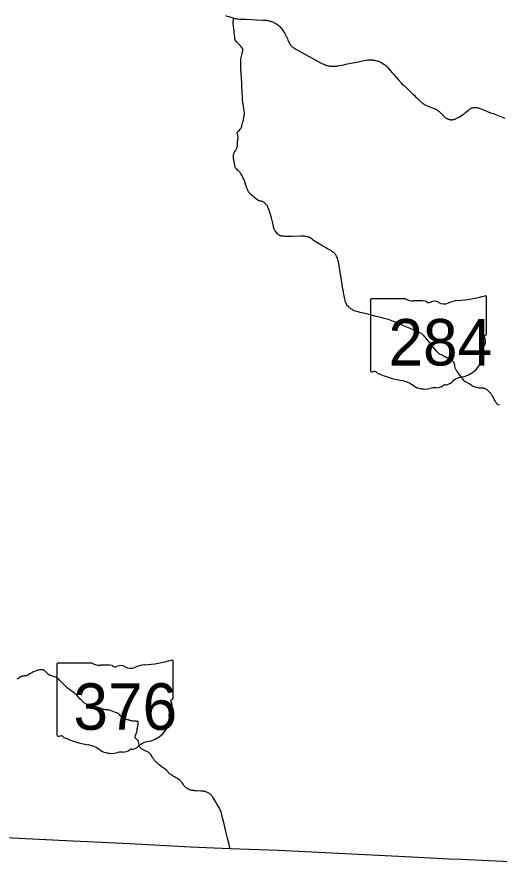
# Model space of a CAD drawing. Extents: x 1761803 to 2441803, y 509895 to 949895.
# Drawn here: x 2145336 to 2174217, y 736190 to 786865 of the extents above; entities that cross this region are included whole.
import ezdxf

# ---------------------------------------------------------------- set-up
doc = ezdxf.new("R2010")
doc.units = 0
for name, color, linetype in [('GM_X_County', 7, 'Continuous'), ('GM_X_Minor_Lake', 7, 'Continuous'), ('GM_X_Township_Road', 7, 'Continuous')]:
    doc.layers.add(name, color=color, linetype=linetype)

msp = doc.modelspace()

# ---------------------------------------------------------------- linework, layer by layer
at = {"layer": 'GM_X_County'}
msp.add_lwpolyline([(2176490, 736190), (2173590, 736330), (2171974, 736412), (2171228, 736429), (2168996, 736548), (2160995, 736937), (2158105, 737039), (2155729, 737139), (2152072, 737341), (2147863, 737541), (2144231, 737722)], dxfattribs=at)
at = {"layer": 'GM_X_Minor_Lake'}
for points in [[(2157833, 786941), (2157929, 786911), (2157991, 786892), (2158085, 786864), (2158271, 786808), (2158333, 786789)], [(2164420, 772630), (2164403, 772654), (2164373, 772693), (2164339, 772730), (2164303, 772764), (2164265, 772795), (2164225, 772825), (2164184, 772852), (2164142, 772878), (2164099, 772901), (2164026, 772938), (2163967, 772966), (2163909, 772996), (2163781, 773068), (2163738, 773093), (2163667, 773134), (2163597, 773176), (2163512, 773226), (2163456, 773259), (2163372, 773310), (2163303, 773354), (2163192, 773424), (2163137, 773460), (2163083, 773497), (2163018, 773546), (2162952, 773595), (2162911, 773622), (2162868, 773647), (2162823, 773669), (2162777, 773687), (2162730, 773702), (2162682, 773713), (2162633, 773721), (2162568, 773727), (2162354, 773728), (2161831, 773716), (2161453, 773719), (2161404, 773720), (2161323, 773725), (2161258, 773731), (2161206, 773739), (2161157, 773747), (2161110, 773760), (2161096, 773766), (2161069, 773776), (2161038, 773794), (2161005, 773821), (2160973, 773851), (2160800, 774045), (2160777, 774078), (2160755, 774114), (2160741, 774147), (2160728, 774185), (2160718, 774221), (2160707, 774280), (2160685, 774426), (2160670, 774506), (2160649, 774602), (2160613, 774745), (2160588, 774839), (2160570, 774902), (2160529, 775026), (2160463, 775212), (2160390, 775435), (2160374, 775475), (2160359, 775506), (2160343, 775535), (2160325, 775562), (2160305, 775588), (2160283, 775613), (2160248, 775648), (2160200, 775693), (2160137, 775747), (2160073, 775795), (2160048, 775805), (2160017, 775812), (2159957, 775828), (2159911, 775836), (2159863, 775849), (2159831, 775859), (2159806, 775871), (2159773, 775886), (2159712, 775926), (2159611, 776008), (2159548, 776061), (2159450, 776147), (2159378, 776213), (2159331, 776258), (2159296, 776293), (2159263, 776329), (2159243, 776354), (2159214, 776394), (2159189, 776433), (2159161, 776484), (2159140, 776521), (2159122, 776560), (2159102, 776611), (2159080, 776679), (2159062, 776736), (2159047, 776806), (2159033, 776860), (2159018, 776910), (2158996, 776970), (2158965, 777045), (2158921, 777151), (2158894, 777211), (2158866, 777270), (2158828, 777343), (2158796, 777400), (2158763, 777457), (2158727, 777512), (2158708, 777539), (2158687, 777564), (2158666, 777589), (2158633, 777625), (2158598, 777660), (2158536, 777714), (2158488, 777759), (2158466, 777782), (2158443, 777805), (2158423, 777832), (2158409, 777858), (2158402, 777884), (2158390, 777933), (2158384, 777981), (2158373, 778049), (2158359, 778128), (2158344, 778192), (2158329, 778256), (2158321, 778304), (2158316, 778353), (2158313, 778403), (2158312, 778453), (2158312, 778569), (2158318, 778622), (2158326, 778660), (2158340, 778697), (2158370, 778757), (2158423, 778854), (2158486, 778971), (2158503, 779012), (2158521, 779063), (2158531, 779102), (2158541, 779147), (2158547, 779211), (2158547, 779314), (2158548, 779365), (2158554, 779405), (2158563, 779459), (2158575, 779527), (2158584, 779580), (2158585, 779611), (2158587, 779647), (2158584, 779682), (2158577, 779724), (2158564, 779769), (2158540, 779846), (2158531, 779881), (2158530, 779905), (2158533, 779928), (2158538, 779944), (2158544, 779958), (2158552, 779972), (2158568, 779992), (2158594, 780020), (2158664, 780091), (2158709, 780136), (2158730, 780161), (2158749, 780189), (2158765, 780217), (2158779, 780248), (2158791, 780278), (2158810, 780341), (2158836, 780436), (2158855, 780515), (2158878, 780611), (2158901, 780706), (2158931, 780834), (2158947, 780915), (2158956, 780963), (2158961, 781013), (2158963, 781046), (2158962, 781079), (2158960, 781112), (2158954, 781161), (2158942, 781242), (2158885, 781644), (2158874, 781742), (2158856, 781905), (2158848, 782003), (2158840, 782166), (2158836, 782248), (2158825, 782441), (2158810, 782716), (2158807, 782781), (2158805, 782829), (2158803, 782876), (2158802, 782907), (2158756, 783764), (2158742, 784069), (2158740, 784151), (2158741, 784216), (2158746, 784282), (2158754, 784363), (2158766, 784444), (2158780, 784510), (2158800, 784598), (2158822, 784675), (2158840, 784750), (2158853, 784810), (2158861, 784859), (2158863, 784875), (2158863, 784892), (2158863, 784909), (2158861, 784925), (2158858, 784941), (2158854, 784958), (2158849, 784973), (2158842, 784989), (2158834, 785003), (2158825, 785017), (2158815, 785030), (2158794, 785055), (2158726, 785126), (2158682, 785174), (2158597, 785273), (2158554, 785321), (2158497, 785379), (2158453, 785427), (2158434, 785453), (2158417, 785480), (2158404, 785509), (2158398, 785524), (2158390, 785555), (2158385, 785587), (2158381, 785619), (2158379, 785667), (2158375, 785788), (2158368, 785855), (2158358, 785937), (2158345, 786025), (2158329, 786138), (2158303, 786350), (2158295, 786431), (2158286, 786496), (2158284, 786529), (2158284, 786561), (2158290, 786609), (2158299, 786657), (2158316, 786721), (2158333, 786789)], [(2158333, 786789), (2158386, 786777), (2158454, 786765), (2158534, 786754), (2158594, 786748)], [(2158594, 786748), (2158596, 786748), (2158715, 786740), (2159059, 786725), (2159682, 786696), (2160059, 786680), (2160190, 786672), (2160256, 786666), (2160321, 786657), (2160386, 786645), (2160450, 786631), (2160513, 786614), (2160576, 786593), (2160637, 786569), (2160697, 786542), (2160751, 786516), (2160797, 786489), (2160842, 786464), (2160898, 786429), (2160952, 786391), (2161003, 786350), (2161054, 786308), (2161102, 786263), (2161147, 786215), (2161191, 786166), (2161232, 786115), (2161271, 786062), (2161327, 785977), (2161351, 785936), (2161380, 785878), (2161445, 785745), (2161535, 785551), (2161569, 785477), (2161624, 785358), (2161660, 785285), (2161683, 785245), (2161711, 785201), (2161730, 785175), (2161762, 785138), (2161797, 785103), (2161833, 785071), (2161873, 785042), (2161928, 785007), (2162042, 784942), (2162631, 784619), (2163019, 784405), (2163027, 784401), (2163566, 784105), (2163653, 784060), (2163712, 784031), (2163772, 784006), (2163833, 783984), (2163896, 783965), (2163975, 783944), (2164039, 783931), (2164104, 783921), (2164185, 783912), (2164250, 783908), (2164315, 783907), (2164381, 783910), (2164446, 783916), (2164511, 783925), (2164640, 783948), (2164913, 784004), (2165041, 784031), (2165346, 784094), (2165555, 784137), (2165667, 784160), (2165780, 784183), (2166165, 784262), (2166246, 784276), (2166328, 784287), (2166393, 784293), (2166459, 784295), (2166525, 784295), (2166591, 784292), (2166646, 784289), (2166703, 784282), (2166758, 784273), (2166820, 784260), (2166888, 784242), (2166949, 784222), (2166993, 784206), (2167039, 784188), (2167086, 784167), (2167134, 784144), (2167165, 784127), (2167211, 784102), (2167256, 784075), (2167313, 784037), (2167367, 783997), (2167427, 783948), (2167464, 783915), (2167510, 783869), (2167611, 783761), (2167697, 783662), (2167813, 783525), (2167856, 783476), (2167911, 783415), (2167974, 783340), (2168049, 783254), (2168168, 783118), (2168332, 782935), (2168399, 782864), (2168492, 782772), (2168682, 782591), (2168825, 782456), (2168867, 782418), (2168921, 782367), (2169076, 782220), (2169125, 782177), (2169220, 782086), (2169268, 782041), (2169411, 781906), (2169580, 781750), (2169629, 781708), (2169668, 781678), (2169722, 781641), (2169777, 781607), (2169821, 781584), (2169880, 781557), (2169971, 781519), (2170109, 781467), (2170325, 781388), (2170386, 781363), (2170430, 781342), (2170473, 781317), (2170514, 781290), (2170553, 781260), (2170603, 781216), (2170792, 781035), (2170875, 780956), (2170950, 780884), (2170987, 780850), (2171019, 780826), (2171061, 780796), (2171101, 780773), (2171150, 780749), (2171197, 780732), (2171241, 780721), (2171278, 780714), (2171316, 780709), (2171360, 780707), (2171407, 780709), (2171444, 780713), (2171485, 780718), (2171506, 780723), (2171518, 780726), (2171546, 780735), (2171583, 780748), (2171623, 780767), (2171668, 780792), (2171768, 780849), (2171839, 780890), (2171936, 780949), (2172033, 781011), (2172113, 781065), (2172166, 781103), (2172230, 781154), (2172359, 781267), (2172421, 781317), (2172462, 781347), (2172503, 781372), (2172540, 781393), (2172571, 781407), (2172601, 781417), (2172633, 781428), (2172667, 781436), (2172717, 781444), (2172762, 781446), (2172799, 781446), (2172838, 781444), (2172882, 781440), (2172912, 781435), (2172940, 781428), (2172968, 781419), (2173026, 781399), (2173057, 781387), (2173243, 781313), (2173501, 781209), (2173761, 781109), (2173853, 781073), (2174554, 780796)], [(2170178, 767204), (2170172, 767211), (2169991, 767443), (2169879, 767584), (2169806, 767673), (2169752, 767733), (2169706, 767780), (2169670, 767814), (2169632, 767846), (2169593, 767876), (2169552, 767904), (2169510, 767929), (2169466, 767953), (2169422, 767974), (2169331, 768013), (2169074, 768120), (2168893, 768196), (2168486, 768371), (2168321, 768443), (2168051, 768563), (2167900, 768628), (2167793, 768670), (2167685, 768709), (2167591, 768740), (2167497, 768767), (2167338, 768809), (2167052, 768880), (2166845, 768933), (2166432, 769040), (2166193, 769099), (2165905, 769164), (2165778, 769195), (2165699, 769216), (2165621, 769241), (2165560, 769264), (2165499, 769289), (2165455, 769311), (2165413, 769334), (2165371, 769361), (2165331, 769389), (2165293, 769419), (2165256, 769451), (2165221, 769485), (2165187, 769521), (2165145, 769571), (2165105, 769623), (2165078, 769663), (2165071, 769677), (2165054, 769706), (2165034, 769750), (2165016, 769796), (2165001, 769842), (2164988, 769889), (2164974, 769953), (2164843, 770680), (2164791, 770987), (2164743, 771311), (2164702, 771587), (2164663, 771847), (2164640, 771976), (2164617, 772089), (2164602, 772154), (2164595, 772185), (2164574, 772264), (2164555, 772327), (2164534, 772389), (2164510, 772450), (2164484, 772511), (2164455, 772570), (2164431, 772613), (2164420, 772630)], [(2174232, 763604), (2174188, 763627), (2174164, 763641), (2174160, 763643), (2174134, 763661), (2174109, 763682), (2174093, 763697), (2174085, 763705), (2174077, 763714), (2174064, 763728), (2174034, 763767), (2174007, 763808), (2173975, 763864), (2173928, 763950), (2173898, 764008), (2173853, 764095), (2173823, 764152), (2173776, 764239), (2173750, 764281), (2173721, 764321), (2173700, 764346), (2173665, 764382), (2173605, 764438), (2173543, 764492), (2173504, 764522), (2173464, 764551), (2173421, 764577), (2173392, 764592), (2173361, 764605), (2173329, 764614), (2173296, 764620), (2173263, 764623), (2173214, 764625), (2173100, 764631), (2173035, 764637), (2172986, 764643), (2172917, 764656), (2172858, 764670), (2172819, 764682), (2172779, 764694), (2172724, 764713), (2172647, 764745), (2172617, 764760), (2172578, 764784), (2172541, 764811), (2172484, 764853), (2172438, 764886), (2172389, 764916), (2172361, 764933), (2172331, 764947), (2172240, 764984), (2172211, 764999), (2172200, 765006), (2172175, 765021), (2172147, 765046), (2172079, 765136), (2172024, 765211), (2171968, 765280), (2171919, 765339), (2171850, 765432), (2171813, 765486), (2171780, 765537), (2171734, 765600), (2171689, 765659), (2171661, 765696), (2171641, 765726), (2171624, 765757), (2171608, 765797), (2171587, 765870), (2171573, 765942), (2171557, 766028), (2171547, 766075), (2171534, 766118), (2171524, 766148), (2171500, 766192), (2171490, 766206), (2171468, 766230), (2171445, 766254), (2171407, 766286), (2171372, 766313), (2171332, 766342), (2171293, 766365), (2171258, 766385), (2171150, 766431), (2171089, 766456), (2171059, 766469), (2171030, 766482), (2171016, 766489), (2171002, 766495), (2170989, 766502), (2170976, 766509), (2170951, 766523), (2170938, 766531), (2170912, 766549), (2170885, 766567), (2170857, 766584), (2170828, 766601), (2170799, 766615), (2170692, 766658), (2170663, 766671), (2170635, 766687), (2170607, 766704), (2170582, 766724), (2170557, 766745), (2170524, 766781), (2170460, 766855), (2170368, 766969), (2170274, 767083), (2170178, 767204)], [(2155235, 740994), (2155230, 741001), (2155201, 741040), (2155180, 741064), (2155146, 741099), (2155110, 741132), (2155060, 741174), (2155008, 741214), (2154968, 741242), (2154913, 741278), (2154843, 741320), (2154773, 741361), (2154701, 741401), (2154649, 741434), (2154607, 741459), (2154549, 741495), (2154509, 741520), (2154472, 741551), (2154445, 741576), (2154421, 741603), (2154386, 741648), (2154347, 741697), (2154323, 741723), (2154289, 741757), (2154239, 741793), (2154149, 741855), (2154087, 741897), (2154037, 741934), (2153996, 741967), (2153942, 742014), (2153936, 742019), (2153866, 742075), (2153815, 742116), (2153750, 742166), (2153698, 742207), (2153674, 742228), (2153653, 742249), (2153650, 742252), (2153618, 742289), (2153589, 742328), (2153560, 742368), (2153532, 742408), (2153503, 742448), (2153479, 742488), (2153425, 742571), (2153387, 742629), (2153353, 742683), (2153328, 742720), (2153304, 742751), (2153274, 742779), (2153247, 742802), (2153218, 742820), (2153176, 742843), (2153120, 742870), (2152979, 742934), (2152930, 742957), (2152892, 742977), (2152866, 742991), (2152836, 743012), (2152803, 743036), (2152760, 743076), (2152724, 743115), (2152704, 743141), (2152687, 743168), (2152668, 743221), (2152652, 743285), (2152630, 743380), (2152612, 743442), (2152601, 743473), (2152589, 743503), (2152574, 743531), (2152565, 743545), (2152546, 743570), (2152524, 743594), (2152488, 743627), (2152451, 743659), (2152439, 743672), (2152430, 743685), (2152429, 743686), (2152421, 743700), (2152416, 743716), (2152412, 743732), (2152411, 743748), (2152414, 743772), (2152421, 743802), (2152432, 743839), (2152450, 743886), (2152478, 743953), (2152497, 744000), (2152516, 744050), (2152530, 744091), (2152539, 744129), (2152542, 744175), (2152546, 744229), (2152552, 744280), (2152559, 744326), (2152571, 744395), (2152584, 744463), (2152593, 744518), (2152600, 744567), (2152605, 744615), (2152608, 744668), (2152575, 744672), (2152545, 744676), (2152525, 744678), (2152473, 744680), (2152395, 744685), (2152315, 744688), (2152251, 744694), (2152205, 744703), (2152177, 744710), (2152141, 744721), (2152095, 744736), (2152048, 744749), (2152010, 744760), (2151957, 744769), (2151902, 744780), (2151870, 744787), (2151838, 744796), (2151807, 744808), (2151777, 744821), (2151748, 744837), (2151720, 744855), (2151679, 744884), (2151645, 744911), (2151604, 744948), (2151540, 745017), (2151495, 745065), (2151461, 745100), (2151435, 745120), (2151407, 745138), (2151368, 745159), (2151314, 745181), (2151180, 745231), (2150887, 745339), (2150826, 745357), (2150800, 745362), (2150775, 745365), (2150744, 745367), (2150687, 745371), (2150628, 745375), (2150581, 745379), (2150551, 745384), (2150524, 745391), (2150494, 745400), (2150443, 745416), (2150386, 745438), (2150324, 745460), (2150262, 745483), (2150199, 745501), (2150152, 745513), (2150065, 745529), (2149994, 745544), (2149909, 745565), (2149831, 745588), (2149595, 745661), (2149532, 745683), (2149475, 745705), (2149444, 745721), (2149414, 745742), (2149380, 745768), (2149341, 745801), (2149304, 745836), (2149245, 745895), (2149222, 745917), (2149197, 745943), (2149110, 746030), (2149042, 746108), (2149002, 746154), (2148937, 746226), (2148898, 746265), (2148863, 746298), (2148827, 746331), (2148775, 746370), (2148677, 746439), (2148590, 746499), (2148478, 746577), (2148416, 746623), (2148371, 746659), (2148336, 746691), (2148290, 746740), (2148195, 746847), (2148149, 746894), (2148091, 746952), (2148011, 747034), (2147895, 747150), (2147848, 747195), (2147811, 747227), (2147785, 747247), (2147744, 747273), (2147701, 747296), (2147649, 747318), (2147576, 747344), (2147363, 747418), (2147322, 747435), (2147284, 747452), (2147254, 747470), (2147226, 747489), (2147195, 747516), (2147147, 747565), (2147088, 747624), (2147052, 747660), (2147027, 747681), (2147000, 747704), (2146976, 747719), (2146947, 747736), (2146930, 747743), (2146904, 747751), (2146870, 747758), (2146840, 747762), (2146815, 747765), (2146792, 747765), (2146772, 747765), (2146752, 747765), (2146737, 747765), (2146722, 747765), (2146713, 747764), (2146701, 747763), (2146681, 747760), (2146636, 747751), (2146591, 747741), (2146536, 747724), (2146464, 747697), (2146421, 747681), (2146382, 747664), (2146338, 747644), (2146287, 747618), (2146230, 747588), (2146109, 747517), (2146022, 747466), (2145977, 747443), (2145932, 747423), (2145902, 747413), (2145867, 747406), (2145843, 747401), (2145819, 747399), (2145785, 747397), (2145746, 747393), (2145717, 747390), (2145684, 747384), (2145658, 747378), (2145627, 747368), (2145597, 747356), (2145554, 747334), (2145511, 747310), (2145442, 747267), (2145407, 747246), (2145368, 747224), (2145324, 747203)], [(2158105, 737039), (2158077, 737165), (2158044, 737309), (2157955, 737676), (2157873, 738011), (2157810, 738266), (2157725, 738617), (2157655, 738904), (2157612, 739079), (2157586, 739174), (2157561, 739252), (2157540, 739314), (2157516, 739375), (2157496, 739419), (2157467, 739478), (2157412, 739579), (2157338, 739707), (2157237, 739876), (2157109, 740086), (2157074, 740141), (2157069, 740147), (2157045, 740181), (2157014, 740219), (2156982, 740255), (2156947, 740290), (2156910, 740322), (2156871, 740351), (2156830, 740379), (2156788, 740404), (2156745, 740425), (2156700, 740444), (2156653, 740460), (2156606, 740473), (2156558, 740483), (2156510, 740491), (2156445, 740498), (2156347, 740504), (2156085, 740517), (2155970, 740523), (2155904, 740530), (2155839, 740539), (2155790, 740549), (2155742, 740561), (2155695, 740577), (2155649, 740595), (2155605, 740616), (2155561, 740641), (2155520, 740668), (2155481, 740698), (2155443, 740730), (2155406, 740763), (2155372, 740799), (2155351, 740825), (2155321, 740864), (2155267, 740946), (2155235, 740994)]]:
    msp.add_lwpolyline(points, dxfattribs=at)
at = {"layer": 'GM_X_Township_Road'}
for p, q in [((2166508, 769918), (2166508, 765691)), ((2168615, 769991), (2166577, 769991)), ((2173469, 767884), (2173469, 770095)), ((2173469, 767885), (2173469, 767884)), ((2147734, 748098), (2147734, 743872)), ((2149841, 748171), (2147803, 748171)), ((2154695, 746065), (2154695, 748276)), ((2154694, 746065), (2154695, 746065))]:
    msp.add_line(p, q, dxfattribs=at)
for centre, major_axis, start_param, end_param in [((2166588, 769927), (80.6, 0), 1.712693, 3.28349), ((2169101, 770481), (782, 0), 4.042523, 4.731795), ((2169360, 767618), (2808, 0), 1.404758, 1.657858), ((2169998, 769949), (226, 0), 3.836095, 5.185415), ((2170329, 769460), (469, 0), 0.950623, 2.079405), ((2170934, 770130), (564, 0), 4.081561, 5.145723), ((2171931, 768700), (1485, 0), 1.699011, 2.107814), ((2170990, 775753), (7382, 0), 4.814394, 5.042369), ((2173392, 770104), (77.5, 0), 6.141152, 7.989035), ((2173451, 767722), (120, 0), 1.883978, 3.671073), ((2173387, 767876), (82.9, 0), 5.05454, 6.418171), ((2173747, 766959), (524, 0), 2.387724, 3.262537), ((2172688, 767443), (720, 0), 5.934695, 6.695948), ((2171403, 766678), (1846, 0), 5.101752, 6.440018), ((2166589, 765682), (81.4, 0), 3.00124, 4.508301), ((2166601, 766114), (621, 0), 4.665946, 4.897461), ((2166728, 765447), (224, 0), 0.519207, 1.627899), ((2169555, 769245), (5331, 0), 4.195997, 4.488961), ((2172182, 764505), (1011, 0), 1.647645, 2.488434), ((2167965, 763792), (1668, 0), 0.823519, 1.323587), ((2169769, 765426), (1058, 0), 4.026481, 4.996735), ((2170458, 765110), (564, 0), 4.691044, 5.507374), ((2170968, 764701), (159, 0), 1.147584, 2.315152), ((2170900, 765282), (597, 0), 4.937069, 5.64225), ((2170381, 763965), (870, 0), 1.495662, 1.94098), ((2147814, 748107), (80.6, 0), 1.712693, 3.28349), ((2150327, 748662), (782, 0), 4.042523, 4.731795), ((2150586, 745798), (2808, 0), 1.404758, 1.657858), ((2151223, 748129), (226, 0), 3.836095, 5.185415), ((2151555, 747641), (469, 0), 0.950623, 2.079405), ((2153157, 746880), (1485, 0), 1.699011, 2.107814), ((2152215, 753933), (7382, 0), 4.814394, 5.042369), ((2154618, 748285), (77.5, 0), 6.141152, 7.989035), ((2152160, 748311), (564, 0), 4.081561, 5.145723), ((2154677, 745903), (120, 0), 1.883978, 3.671073), ((2154612, 746056), (82.9, 0), 5.05454, 6.418171), ((2153914, 745623), (720, 0), 5.934695, 6.695948), ((2152629, 744858), (1846, 0), 5.101752, 6.440018), ((2154972, 745140), (524, 0), 2.387724, 3.262537), ((2147814, 743863), (81.4, 0), 3.00124, 4.508301), ((2147827, 744295), (621, 0), 4.665946, 4.897461), ((2147954, 743628), (224, 0), 0.519207, 1.627899), ((2150780, 747425), (5331, 0), 4.195997, 4.488961), ((2153407, 742685), (1011, 0), 1.647645, 2.488434), ((2149191, 741973), (1668, 0), 0.823519, 1.323587), ((2150995, 743607), (1058, 0), 4.026481, 4.996735), ((2151684, 743291), (564, 0), 4.691044, 5.507374), ((2152194, 742881), (159, 0), 1.147584, 2.315152), ((2152126, 743462), (597, 0), 4.937069, 5.64225), ((2151606, 742146), (870, 0), 1.495662, 1.94098)]:
    msp.add_ellipse(centre, major_axis=major_axis, ratio=0.8, start_param=start_param, end_param=end_param, dxfattribs=at)

# ---------------------------------------------------------------- texts
for s, p in [('284', (2167588, 765989)), ('376', (2148721, 744170))]:
    msp.add_text(s, height=2784.4, dxfattribs=at).set_placement(p)

doc.saveas('drawing.dxf')
